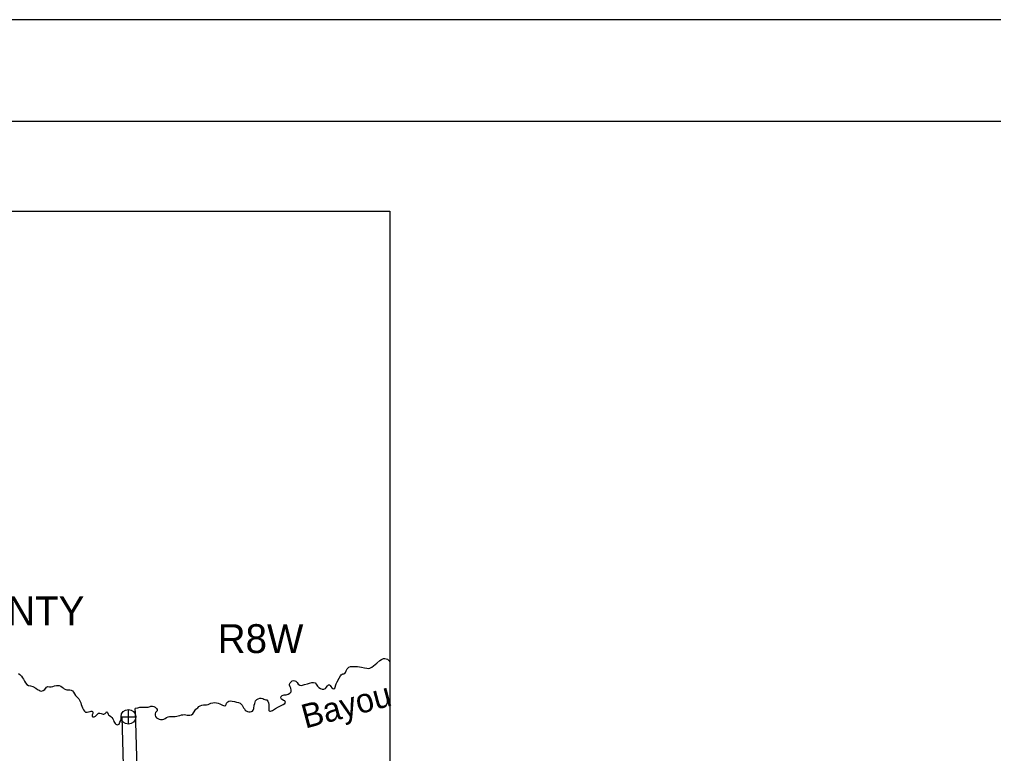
# Model space of a CAD drawing. Extents: x 1367863 to 1368197, y 380048 to 380261.
# Drawn here: x 1367923.7 to 1367960.97, y 380233.33 to 380261.43 of the extents above; entities that cross this region are included whole.
import ezdxf

# ---------------------------------------------------------------- set-up
doc = ezdxf.new("R2010")
doc.units = 0
for name, color, linetype in [('Level 10', 7, 'Continuous'), ('Level 2', 7, 'Continuous'), ('Level 26', 7, 'Continuous'), ('Level 30', 7, 'Continuous'), ('Level 9', 7, 'Continuous'), ('R_Border', 7, 'Continuous'), ('R_No Plot', 7, 'Continuous')]:
    doc.layers.add(name, color=color, linetype=linetype)

msp = doc.modelspace()

# ---------------------------------------------------------------- linework, layer by layer
at = {"layer": 'Level 10'}
for points in [[(1367928.125, 380234.976), (1367928.121, 380235.06)], [(1367928.125, 380234.972), (1367928.26, 380230.12), (1367928.34, 380226.984)], [(1367927.609, 380234.741), (1367927.738, 380230.106), (1367927.738, 380230.104)]]:
    msp.add_lwpolyline(points, dxfattribs=at)
at = {"layer": 'Level 2'}
for points in [[(1367936.143, 380236.402), (1367936.17, 380236.434), (1367936.193, 380236.494), (1367936.232, 380236.574), (1367936.298, 380236.637), (1367936.362, 380236.658), (1367936.459, 380236.663), (1367936.63, 380236.666), (1367936.788, 380236.638), (1367936.898, 380236.615), (1367936.989, 380236.597), (1367937.054, 380236.59), (1367937.109, 380236.604), (1367937.181, 380236.642), (1367937.368, 380236.793), (1367937.491, 380236.893), (1367937.549, 380236.933), (1367937.628, 380236.966), (1367937.673, 380236.966), (1367937.733, 380236.959), (1367937.785, 380236.94), (1367937.846, 380236.88), (1367937.876, 380236.843)], [(1367923.658, 380236.39), (1367923.71, 380236.36), (1367923.776, 380236.297), (1367923.817, 380236.234), (1367923.847, 380236.177), (1367923.885, 380236.103), (1367923.93, 380236.036), (1367923.98, 380235.98), (1367924.044, 380235.941), (1367924.123, 380235.929), (1367924.214, 380235.899), (1367924.329, 380235.835), (1367924.391, 380235.79), (1367924.446, 380235.76), (1367924.492, 380235.737), (1367924.542, 380235.726), (1367924.599, 380235.743), (1367924.664, 380235.788), (1367924.737, 380235.867), (1367924.778, 380235.893), (1367924.851, 380235.889), (1367924.909, 380235.887), (1367924.975, 380235.896), (1367925.039, 380235.919), (1367925.12, 380235.94), (1367925.216, 380235.932), (1367925.277, 380235.915), (1367925.332, 380235.879), (1367925.373, 380235.844), (1367925.414, 380235.808), (1367925.472, 380235.778), (1367925.516, 380235.769), (1367925.573, 380235.769), (1367925.626, 380235.765), (1367925.677, 380235.752), (1367925.722, 380235.727), (1367925.76, 380235.678), (1367925.798, 380235.618), (1367925.84, 380235.554), (1367925.879, 380235.51), (1367925.935, 380235.462), (1367925.972, 380235.421)], [(1367932.303, 380235.038), (1367932.339, 380234.999), (1367932.378, 380234.967), (1367932.429, 380234.942), (1367932.475, 380234.933), (1367932.525, 380234.933), (1367932.579, 380234.94), (1367932.619, 380234.96), (1367932.644, 380234.997), (1367932.661, 380235.052), (1367932.683, 380235.189), (1367932.701, 380235.242), (1367932.713, 380235.293), (1367932.734, 380235.344), (1367932.778, 380235.399), (1367932.828, 380235.432), (1367932.891, 380235.452), (1367932.949, 380235.455), (1367933.009, 380235.438), (1367933.055, 380235.409), (1367933.092, 380235.398), (1367933.127, 380235.394), (1367933.16, 380235.385), (1367933.196, 380235.338), (1367933.228, 380235.271), (1367933.242, 380235.207), (1367933.239, 380235.12), (1367933.234, 380235.067), (1367933.234, 380235.013), (1367933.24, 380234.984), (1367933.254, 380234.961), (1367933.274, 380234.95), (1367933.307, 380234.949), (1367933.381, 380234.986), (1367933.49, 380235.061), (1367933.608, 380235.126), (1367933.71, 380235.172), (1367933.792, 380235.215), (1367933.847, 380235.251), (1367933.873, 380235.291), (1367933.871, 380235.324), (1367933.849, 380235.344), (1367933.807, 380235.365), (1367933.747, 380235.395), (1367933.72, 380235.42), (1367933.703, 380235.464), (1367933.712, 380235.514), (1367933.756, 380235.559), (1367933.825, 380235.581), (1367933.906, 380235.585), (1367933.984, 380235.605), (1367934.049, 380235.641), (1367934.091, 380235.7), (1367934.095, 380235.755), (1367934.077, 380235.831), (1367934.054, 380235.891), (1367934.037, 380235.948), (1367934.035, 380235.994), (1367934.052, 380236.038), (1367934.089, 380236.083), (1367934.136, 380236.117), (1367934.185, 380236.124), (1367934.23, 380236.116), (1367934.273, 380236.097), (1367934.318, 380236.046), (1367934.366, 380235.991), (1367934.425, 380235.951), (1367934.493, 380235.941), (1367934.609, 380235.972), (1367934.716, 380236.005), (1367934.794, 380236.028), (1367934.88, 380236.048), (1367934.955, 380236.052), (1367935.015, 380236.037), (1367935.056, 380235.989), (1367935.102, 380235.917), (1367935.158, 380235.861), (1367935.216, 380235.823), (1367935.28, 380235.799), (1367935.342, 380235.797), (1367935.404, 380235.827), (1367935.443, 380235.868), (1367935.468, 380235.914), (1367935.488, 380235.943), (1367935.519, 380235.959), (1367935.557, 380235.959), (1367935.591, 380235.932), (1367935.616, 380235.894), (1367935.651, 380235.848), (1367935.692, 380235.82), (1367935.73, 380235.814), (1367935.763, 380235.841), (1367935.819, 380236.007), (1367935.856, 380236.083), (1367935.926, 380236.214), (1367935.977, 380236.306), (1367936.009, 380236.342), (1367936.046, 380236.373), (1367936.07, 380236.388), (1367936.105, 380236.389), (1367936.143, 380236.402)], [(1367925.972, 380235.421), (1367926.013, 380235.344), (1367926.042, 380235.273), (1367926.061, 380235.212), (1367926.087, 380235.143), (1367926.11, 380235.078), (1367926.148, 380235.005), (1367926.186, 380234.956), (1367926.229, 380234.92), (1367926.286, 380234.913), (1367926.335, 380234.923), (1367926.401, 380234.939), (1367926.446, 380234.95), (1367926.47, 380234.953), (1367926.493, 380234.944), (1367926.507, 380234.917), (1367926.502, 380234.868), (1367926.484, 380234.815), (1367926.478, 380234.776), (1367926.486, 380234.749), (1367926.51, 380234.734), (1367926.556, 380234.733), (1367926.612, 380234.759), (1367926.648, 380234.795), (1367926.68, 380234.838), (1367926.719, 380234.872), (1367926.775, 380234.879), (1367926.824, 380234.864), (1367926.863, 380234.848), (1367926.898, 380234.838), (1367926.931, 380234.839), (1367926.958, 380234.849), (1367926.977, 380234.866), (1367926.991, 380234.883), (1367927.011, 380234.909), (1367927.031, 380234.933), (1367927.047, 380234.935), (1367927.07, 380234.907), (1367927.086, 380234.843), (1367927.111, 380234.814), (1367927.141, 380234.785), (1367927.189, 380234.748), (1367927.237, 380234.709), (1367927.273, 380234.661), (1367927.297, 380234.606), (1367927.312, 380234.563), (1367927.331, 380234.52), (1367927.354, 380234.482), (1367927.384, 380234.456), (1367927.414, 380234.443), (1367927.442, 380234.437), (1367927.475, 380234.438)], [(1367928.125, 380235.067), (1367928.144, 380235.069), (1367928.224, 380235.086), (1367928.302, 380235.102), (1367928.389, 380235.108), (1367928.483, 380235.106), (1367928.561, 380235.106), (1367928.627, 380235.113), (1367928.693, 380235.129), (1367928.731, 380235.141), (1367928.788, 380235.148), (1367928.842, 380235.137), (1367928.894, 380235.113), (1367928.939, 380235.062), (1367928.961, 380235.015), (1367928.971, 380234.986), (1367928.966, 380234.961), (1367928.941, 380234.938), (1367928.909, 380234.902), (1367928.891, 380234.858), (1367928.891, 380234.797), (1367928.903, 380234.746), (1367928.937, 380234.7), (1367928.989, 380234.67), (1367929.042, 380234.644), (1367929.096, 380234.635), (1367929.169, 380234.637), (1367929.228, 380234.653), (1367929.274, 380234.679), (1367929.33, 380234.715), (1367929.382, 380234.741), (1367929.437, 380234.755), (1367929.516, 380234.751), (1367929.566, 380234.747), (1367929.606, 380234.745), (1367929.657, 380234.753), (1367929.716, 380234.764), (1367929.774, 380234.777), (1367929.835, 380234.793), (1367929.899, 380234.809), (1367929.947, 380234.819), (1367929.996, 380234.824), (1367930.064, 380234.818), (1367930.118, 380234.805), (1367930.166, 380234.798), (1367930.214, 380234.801), (1367930.28, 380234.82), (1367930.326, 380234.852), (1367930.361, 380234.896), (1367930.452, 380235.025), (1367930.518, 380235.082), (1367930.565, 380235.127), (1367930.611, 380235.159), (1367930.673, 380235.19), (1367930.737, 380235.197), (1367930.79, 380235.195), (1367930.852, 380235.202), (1367930.913, 380235.213), (1367930.968, 380235.232), (1367931.027, 380235.255), (1367931.103, 380235.276), (1367931.167, 380235.285), (1367931.238, 380235.278), (1367931.3, 380235.263), (1367931.362, 380235.235), (1367931.418, 380235.21), (1367931.471, 380235.188), (1367931.51, 380235.171), (1367931.552, 380235.162), (1367931.573, 380235.164), (1367931.589, 380235.186), (1367931.603, 380235.214), (1367931.622, 380235.257), (1367931.64, 380235.292), (1367931.671, 380235.314), (1367931.704, 380235.332), (1367931.723, 380235.34), (1367931.769, 380235.347), (1367931.836, 380235.342), (1367931.922, 380235.323), (1367932.002, 380235.305), (1367932.085, 380235.284), (1367932.138, 380235.256), (1367932.175, 380235.233), (1367932.218, 380235.187), (1367932.248, 380235.134), (1367932.274, 380235.084), (1367932.303, 380235.038)], [(1367927.475, 380234.438), (1367927.511, 380234.462), (1367927.54, 380234.528), (1367927.571, 380234.598), (1367927.593, 380234.674), (1367927.599, 380234.711)]]:
    msp.add_lwpolyline(points, dxfattribs=at)
at = {"layer": 'Level 26'}
for p, q in [((1367927.867, 380234.454), (1367927.867, 380235.02)), ((1367927.584, 380234.737), (1367928.15, 380234.737))]:
    msp.add_line(p, q, dxfattribs=at)
msp.add_circle((1367927.867, 380234.737), 0.283, dxfattribs=at)
at = {"layer": 'R_Border'}
msp.add_line((1367875.8, 380257.536), (1368191.969, 380257.536), dxfattribs=at)
at = {"layer": 'R_No Plot'}
for p in [(1367863.388, 380261.431), (1367863.4, 380261.431)]:
    msp.add_line(p, (1368196.721, 380261.431), dxfattribs=at)
for points in [[(1367863.393, 380261.431), (1368196.721, 380261.431), (1368196.721, 380048.101), (1367863.393, 380048.101)], [(1367878.711, 380254.093), (1367937.876, 380254.093), (1367937.876, 380187.495), (1367878.711, 380187.495)]]:
    msp.add_lwpolyline(points, close=True, dxfattribs=at)

# ---------------------------------------------------------------- texts
at = {"layer": 'Level 30'}
for s, p in [('COUNTY', (1367919.953, 380238.242)), ('R8W', (1367931.284, 380237.18))]:
    msp.add_text(s, height=1.1032, dxfattribs=at).set_placement(p)
at = {"layer": 'Level 9'}
msp.add_text('Bayou', height=0.9194, rotation=15, dxfattribs=at).set_placement((1367934.636, 380234.283))

doc.saveas('drawing.dxf')
